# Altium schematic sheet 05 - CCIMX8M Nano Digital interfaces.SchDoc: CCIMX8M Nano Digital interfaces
size A3; PageSetup: Record=PageOptions¦CenterHorizontal=True¦CenterVertical=True¦PrintScale=0.70¦XCorrection=1.00¦YCorrection=1.00¦PrintKind=0¦BorderSize=5000000¦LeftOffset=0¦BottomOffset=0¦Orientation=2¦PaperLength=4200¦PaperWidth=2970¦Scale=100¦PaperSource=7¦PrintQuality=600¦MediaType=1¦DitherType=10¦PaperKind=A4¦PrintScaleMode=1; Author: Juan Anzola; SheetNumber: 5; SheetTotal: 21
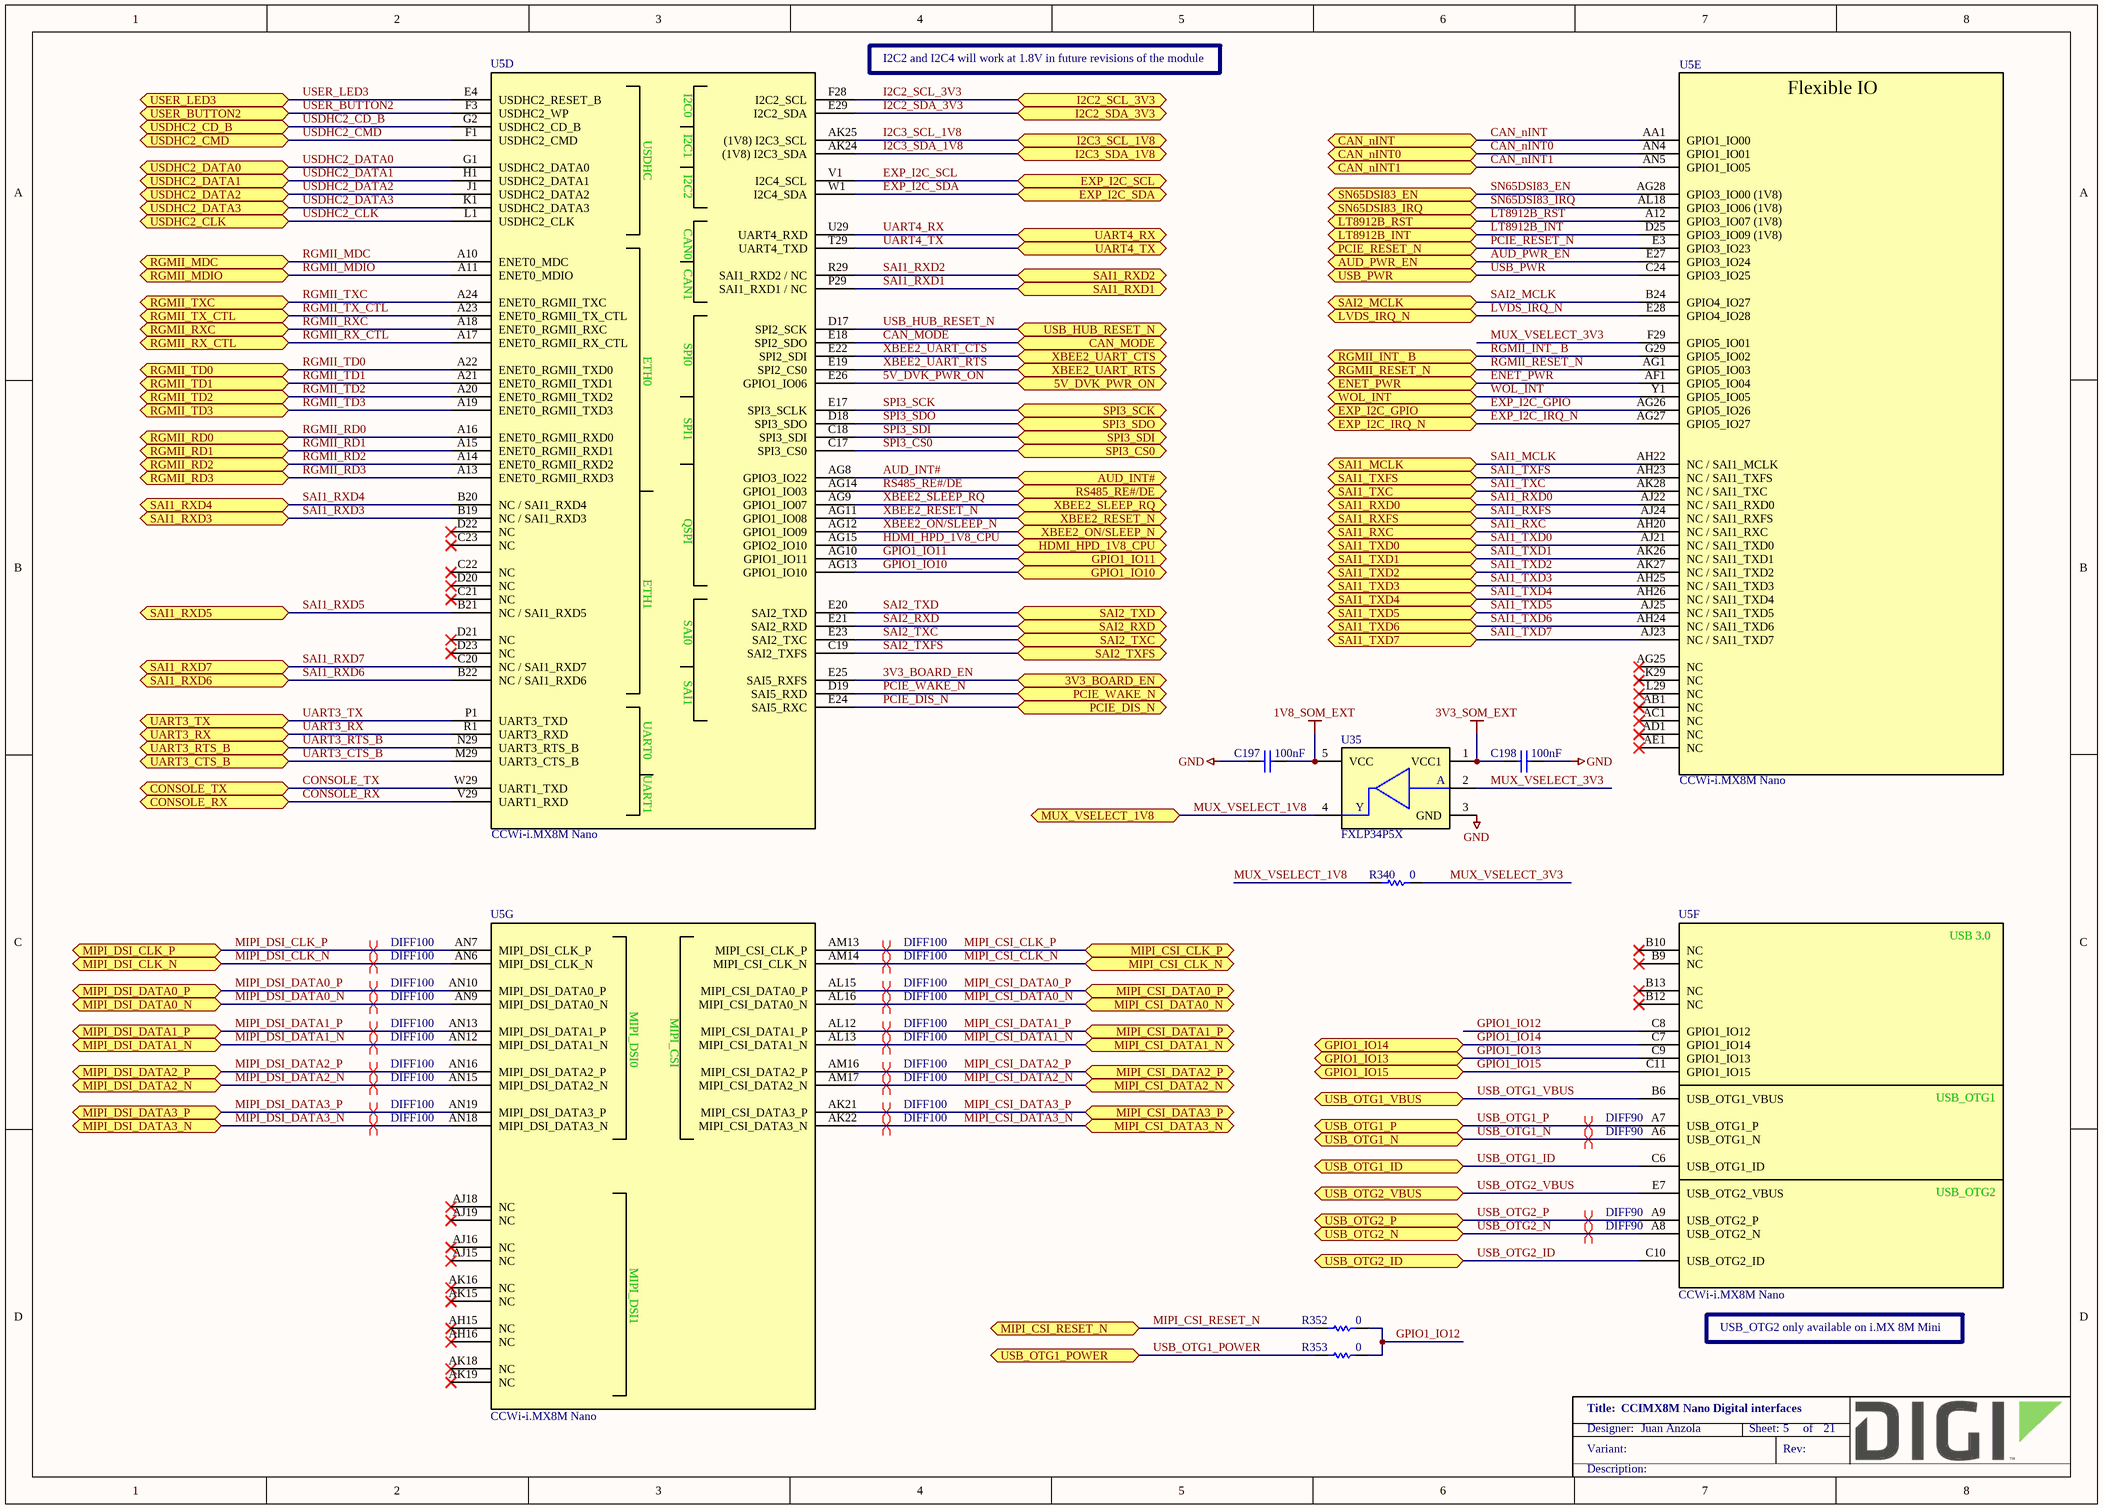
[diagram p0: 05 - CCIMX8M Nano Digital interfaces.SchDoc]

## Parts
C197  100nF  [CAPC1005X55N]
C198  100nF  [CAPC1005X55N]
R340  0  [RESC1005X40N]
R352  0  [RESC1005X40N]
R353  0  [RESC1005X40N]
U5  CCWi-i.MX8M Nano  [E-TEC_LPJ474-129M-32ABEW55L]  (parts D,E,F,G of 10)
U35  FXLP34P5X  [SOT65P210X110-5N]

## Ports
3V3_BOARD_EN (bidir), 5V_DVK_PWR_ON (bidir), AUD_INT# (bidir), AUD_PWR_EN (bidir), CAN_MODE (bidir), CAN_nINT0 (bidir), CAN_nINT1 (bidir), CAN_nINT (bidir), CONSOLE_RX (bidir), CONSOLE_TX (bidir), ENET_PWR (bidir), EXP_I2C_GPIO (bidir), EXP_I2C_IRQ_N (bidir), EXP_I2C_SCL (bidir), EXP_I2C_SDA (bidir), GPIO1_IO10 (bidir), GPIO1_IO11 (bidir), GPIO1_IO13 (bidir), GPIO1_IO14 (bidir), GPIO1_IO15 (bidir), HDMI_HPD_1V8_CPU (bidir), I2C2_SCL_3V3 (bidir), I2C2_SDA_3V3 (bidir), I2C3_SCL_1V8 (bidir), I2C3_SDA_1V8 (bidir), LT8912B_INT (bidir), LT8912B_RST (bidir), LVDS_IRQ_N (bidir), MIPI_CSI_CLK_N (bidir), MIPI_CSI_CLK_P (bidir), MIPI_CSI_DATA0_N (bidir), MIPI_CSI_DATA0_P (bidir), MIPI_CSI_DATA1_N (bidir), MIPI_CSI_DATA1_P (bidir), MIPI_CSI_DATA2_N (bidir), MIPI_CSI_DATA2_P (bidir), MIPI_CSI_DATA3_N (bidir), MIPI_CSI_DATA3_P (bidir), MIPI_CSI_RESET_N (bidir), MIPI_DSI_CLK_N (bidir), MIPI_DSI_CLK_P (bidir), MIPI_DSI_DATA0_N (bidir), MIPI_DSI_DATA0_P (bidir), MIPI_DSI_DATA1_N (bidir), MIPI_DSI_DATA1_P (bidir), MIPI_DSI_DATA2_N (bidir), MIPI_DSI_DATA2_P (bidir), MIPI_DSI_DATA3_N (bidir), MIPI_DSI_DATA3_P (bidir), MUX_VSELECT_1V8 (bidir), PCIE_DIS_N (bidir), PCIE_RESET_N (bidir), PCIE_WAKE_N (bidir), RGMII_INT_ B (bidir), RGMII_MDC (bidir), RGMII_MDIO (bidir), RGMII_RD0 (bidir), RGMII_RD1 (bidir), RGMII_RD2 (bidir), RGMII_RD3 (bidir), RGMII_RESET_N (bidir), RGMII_RX_CTL (bidir), RGMII_RXC (bidir), RGMII_TD0 (bidir), RGMII_TD1 (bidir), RGMII_TD2 (bidir), RGMII_TD3 (bidir), RGMII_TX_CTL (bidir), RGMII_TXC (bidir), RS485_RE#/DE (bidir), SAI1_MCLK (bidir), SAI1_RXC (bidir), SAI1_RXD0 (bidir), SAI1_RXD1 (bidir), SAI1_RXD2 (bidir), SAI1_RXD3 (bidir), SAI1_RXD4 (bidir), SAI1_RXD5 (bidir), SAI1_RXD6 (bidir), SAI1_RXD7 (bidir), SAI1_RXFS (bidir), SAI1_TXC (bidir), SAI1_TXD0 (bidir), SAI1_TXD1 (bidir), SAI1_TXD2 (bidir), SAI1_TXD3 (bidir), SAI1_TXD4 (bidir), SAI1_TXD5 (bidir), SAI1_TXD6 (bidir), SAI1_TXD7 (bidir), SAI1_TXFS (bidir), SAI2_MCLK (bidir), SAI2_RXD (bidir), SAI2_TXC (bidir), SAI2_TXD (bidir), SAI2_TXFS (bidir), SN65DSI83_EN (bidir), SN65DSI83_IRQ (bidir), SPI3_CS0 (bidir), SPI3_SCK (bidir), SPI3_SDI (bidir), SPI3_SDO (bidir), UART3_CTS_B (bidir), UART3_RTS_B (bidir), UART3_RX (bidir), UART3_TX (bidir), UART4_RX (bidir), UART4_TX (bidir), USB_HUB_RESET_N (bidir), USB_OTG1_ID (bidir), USB_OTG1_N (bidir), USB_OTG1_P (bidir), USB_OTG1_POWER (bidir), USB_OTG1_VBUS (bidir), USB_OTG2_ID (bidir), USB_OTG2_N (bidir), USB_OTG2_P (bidir), USB_OTG2_VBUS (bidir), USB_PWR (bidir), USDHC2_CD_B (bidir), USDHC2_CLK (bidir), USDHC2_CMD (bidir), USDHC2_DATA0 (bidir), USDHC2_DATA1 (bidir), USDHC2_DATA2 (bidir), USDHC2_DATA3 (bidir), USER_BUTTON2 (bidir), USER_LED3 (bidir), WOL_INT (bidir), XBEE2_ON/SLEEP_N (bidir), XBEE2_RESET_N (bidir), XBEE2_SLEEP_RQ (bidir), XBEE2_UART_CTS (bidir), XBEE2_UART_RTS (bidir)

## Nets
1V8_SOM_EXT: C197.2 U35.5(VCC)
3V3_SOM_EXT: C198.1 U35.1(VCC1)
GND: C197.1 C198.2 U35.3(GND)
3V3_BOARD_EN: U5.E25(SAI5_RXFS) ; port 3V3_BOARD_EN
5V_DVK_PWR_ON: U5.E26(GPIO1_IO06) ; port 5V_DVK_PWR_ON
AUD_INT#: U5.AG8(GPIO3_IO22) ; port AUD_INT#
AUD_PWR_EN: U5.E27(GPIO3_IO24) ; port AUD_PWR_EN
CAN_MODE: U5.E18(SPI2_SDO) ; port CAN_MODE
CAN_nINT: U5.AA1(GPIO1_IO00) ; port CAN_nINT
CAN_nINT0: U5.AN4(GPIO1_IO01) ; port CAN_nINT0
CAN_nINT1: U5.AN5(GPIO1_IO05) ; port CAN_nINT1
CONSOLE_RX: U5.V29(UART1_RXD) ; port CONSOLE_RX
CONSOLE_TX: U5.W29(UART1_TXD) ; port CONSOLE_TX
ENET_PWR: U5.AF1(GPIO5_IO04) ; port ENET_PWR
EXP_I2C_GPIO: U5.AG26(GPIO5_IO26) ; port EXP_I2C_GPIO
EXP_I2C_IRQ_N: U5.AG27(GPIO5_IO27) ; port EXP_I2C_IRQ_N
EXP_I2C_SCL: U5.V1(I2C4_SCL) ; port EXP_I2C_SCL
EXP_I2C_SDA: U5.W1(I2C4_SDA) ; port EXP_I2C_SDA
GPIO1_IO10: U5.AG13(GPIO1_IO10) ; port GPIO1_IO10
GPIO1_IO11: U5.AG10(GPIO1_IO11) ; port GPIO1_IO11
GPIO1_IO12: R352.2 R353.2 U5.C8(GPIO1_IO12)
GPIO1_IO13: U5.C9(GPIO1_IO13) ; port GPIO1_IO13
GPIO1_IO14: U5.C7(GPIO1_IO14) ; port GPIO1_IO14
GPIO1_IO15: U5.C11(GPIO1_IO15) ; port GPIO1_IO15
HDMI_HPD_1V8_CPU: U5.AG15(GPIO2_IO10) ; port HDMI_HPD_1V8_CPU
I2C2_SCL_3V3: U5.F28(I2C2_SCL) ; port I2C2_SCL_3V3
I2C2_SDA_3V3: U5.E29(I2C2_SDA) ; port I2C2_SDA_3V3
I2C3_SCL_1V8: U5.AK25((1V8)_I2C3_SCL) ; port I2C3_SCL_1V8
I2C3_SDA_1V8: U5.AK24((1V8)_I2C3_SDA) ; port I2C3_SDA_1V8
LT8912B_INT: U5.D25(GPIO3_IO09_(1V8)) ; port LT8912B_INT
LT8912B_RST: U5.A12(GPIO3_IO07_(1V8)) ; port LT8912B_RST
LVDS_IRQ_N: U5.E28(GPIO4_IO28) ; port LVDS_IRQ_N
MIPI_CSI_CLK_N: U5.AM14(MIPI_CSI_CLK_N) ; port MIPI_CSI_CLK_N
MIPI_CSI_CLK_P: U5.AM13(MIPI_CSI_CLK_P) ; port MIPI_CSI_CLK_P
MIPI_CSI_DATA0_N: U5.AL16(MIPI_CSI_DATA0_N) ; port MIPI_CSI_DATA0_N
MIPI_CSI_DATA0_P: U5.AL15(MIPI_CSI_DATA0_P) ; port MIPI_CSI_DATA0_P
MIPI_CSI_DATA1_N: U5.AL13(MIPI_CSI_DATA1_N) ; port MIPI_CSI_DATA1_N
MIPI_CSI_DATA1_P: U5.AL12(MIPI_CSI_DATA1_P) ; port MIPI_CSI_DATA1_P
MIPI_CSI_DATA2_N: U5.AM17(MIPI_CSI_DATA2_N) ; port MIPI_CSI_DATA2_N
MIPI_CSI_DATA2_P: U5.AM16(MIPI_CSI_DATA2_P) ; port MIPI_CSI_DATA2_P
MIPI_CSI_DATA3_N: U5.AK22(MIPI_CSI_DATA3_N) ; port MIPI_CSI_DATA3_N
MIPI_CSI_DATA3_P: U5.AK21(MIPI_CSI_DATA3_P) ; port MIPI_CSI_DATA3_P
MIPI_CSI_RESET_N: R352.1 ; port MIPI_CSI_RESET_N
MIPI_DSI_CLK_N: U5.AN6(MIPI_DSI_CLK_N) ; port MIPI_DSI_CLK_N
MIPI_DSI_CLK_P: U5.AN7(MIPI_DSI_CLK_P) ; port MIPI_DSI_CLK_P
MIPI_DSI_DATA0_N: U5.AN9(MIPI_DSI_DATA0_N) ; port MIPI_DSI_DATA0_N
MIPI_DSI_DATA0_P: U5.AN10(MIPI_DSI_DATA0_P) ; port MIPI_DSI_DATA0_P
MIPI_DSI_DATA1_N: U5.AN12(MIPI_DSI_DATA1_N) ; port MIPI_DSI_DATA1_N
MIPI_DSI_DATA1_P: U5.AN13(MIPI_DSI_DATA1_P) ; port MIPI_DSI_DATA1_P
MIPI_DSI_DATA2_N: U5.AN15(MIPI_DSI_DATA2_N) ; port MIPI_DSI_DATA2_N
MIPI_DSI_DATA2_P: U5.AN16(MIPI_DSI_DATA2_P) ; port MIPI_DSI_DATA2_P
MIPI_DSI_DATA3_N: U5.AN18(MIPI_DSI_DATA3_N) ; port MIPI_DSI_DATA3_N
MIPI_DSI_DATA3_P: U5.AN19(MIPI_DSI_DATA3_P) ; port MIPI_DSI_DATA3_P
MUX_VSELECT_1V8: R340.1 U35.4(Y) ; port MUX_VSELECT_1V8
MUX_VSELECT_3V3: R340.2 U5.F29(GPIO5_IO01) U35.2(A)
PCIE_DIS_N: U5.E24(SAI5_RXC) ; port PCIE_DIS_N
PCIE_RESET_N: U5.E3(GPIO3_IO23) ; port PCIE_RESET_N
PCIE_WAKE_N: U5.D19(SAI5_RXD) ; port PCIE_WAKE_N
RGMII_INT_ B: U5.G29(GPIO5_IO02) ; port RGMII_INT_ B
RGMII_MDC: U5.A10(ENET0_MDC) ; port RGMII_MDC
RGMII_MDIO: U5.A11(ENET0_MDIO) ; port RGMII_MDIO
RGMII_RD0: U5.A16(ENET0_RGMII_RXD0) ; port RGMII_RD0
RGMII_RD1: U5.A15(ENET0_RGMII_RXD1) ; port RGMII_RD1
RGMII_RD2: U5.A14(ENET0_RGMII_RXD2) ; port RGMII_RD2
RGMII_RD3: U5.A13(ENET0_RGMII_RXD3) ; port RGMII_RD3
RGMII_RESET_N: U5.AG1(GPIO5_IO03) ; port RGMII_RESET_N
RGMII_RX_CTL: U5.A17(ENET0_RGMII_RX_CTL) ; port RGMII_RX_CTL
RGMII_RXC: U5.A18(ENET0_RGMII_RXC) ; port RGMII_RXC
RGMII_TD0: U5.A22(ENET0_RGMII_TXD0) ; port RGMII_TD0
RGMII_TD1: U5.A21(ENET0_RGMII_TXD1) ; port RGMII_TD1
RGMII_TD2: U5.A20(ENET0_RGMII_TXD2) ; port RGMII_TD2
RGMII_TD3: U5.A19(ENET0_RGMII_TXD3) ; port RGMII_TD3
RGMII_TX_CTL: U5.A23(ENET0_RGMII_TX_CTL) ; port RGMII_TX_CTL
RGMII_TXC: U5.A24(ENET0_RGMII_TXC) ; port RGMII_TXC
RS485_RE#/DE: U5.AG14(GPIO1_IO03) ; port RS485_RE#/DE
SAI1_MCLK: U5.AH22(NC_/_SAI1_MCLK) ; port SAI1_MCLK
SAI1_RXC: U5.AH20(NC_/_SAI1_RXC) ; port SAI1_RXC
SAI1_RXD0: U5.AJ22(NC_/_SAI1_RXD0) ; port SAI1_RXD0
SAI1_RXD1: U5.P29(SAI1_RXD1_/_NC) ; port SAI1_RXD1
SAI1_RXD2: U5.R29(SAI1_RXD2_/_NC) ; port SAI1_RXD2
SAI1_RXD3: U5.B19(NC_/_SAI1_RXD3) ; port SAI1_RXD3
SAI1_RXD4: U5.B20(NC_/_SAI1_RXD4) ; port SAI1_RXD4
SAI1_RXD5: U5.B21(NC_/_SAI1_RXD5) ; port SAI1_RXD5
SAI1_RXD6: U5.B22(NC_/_SAI1_RXD6) ; port SAI1_RXD6
SAI1_RXD7: U5.C20(NC_/_SAI1_RXD7) ; port SAI1_RXD7
SAI1_RXFS: U5.AJ24(NC_/_SAI1_RXFS) ; port SAI1_RXFS
SAI1_TXC: U5.AK28(NC_/_SAI1_TXC) ; port SAI1_TXC
SAI1_TXD0: U5.AJ21(NC_/_SAI1_TXD0) ; port SAI1_TXD0
SAI1_TXD1: U5.AK26(NC_/_SAI1_TXD1) ; port SAI1_TXD1
SAI1_TXD2: U5.AK27(NC_/_SAI1_TXD2) ; port SAI1_TXD2
SAI1_TXD3: U5.AH25(NC_/_SAI1_TXD3) ; port SAI1_TXD3
SAI1_TXD4: U5.AH26(NC_/_SAI1_TXD4) ; port SAI1_TXD4
SAI1_TXD5: U5.AJ25(NC_/_SAI1_TXD5) ; port SAI1_TXD5
SAI1_TXD6: U5.AH24(NC_/_SAI1_TXD6) ; port SAI1_TXD6
SAI1_TXD7: U5.AJ23(NC_/_SAI1_TXD7) ; port SAI1_TXD7
SAI1_TXFS: U5.AH23(NC_/_SAI1_TXFS) ; port SAI1_TXFS
SAI2_MCLK: U5.B24(GPIO4_IO27) ; port SAI2_MCLK
SAI2_RXD: U5.E21(SAI2_RXD) ; port SAI2_RXD
SAI2_TXC: U5.E23(SAI2_TXC) ; port SAI2_TXC
SAI2_TXD: U5.E20(SAI2_TXD) ; port SAI2_TXD
SAI2_TXFS: U5.C19(SAI2_TXFS) ; port SAI2_TXFS
SN65DSI83_EN: U5.AG28(GPIO3_IO00_(1V8)) ; port SN65DSI83_EN
SN65DSI83_IRQ: U5.AL18(GPIO3_IO06_(1V8)) ; port SN65DSI83_IRQ
SPI3_CS0: U5.C17(SPI3_CS0) ; port SPI3_CS0
SPI3_SCK: U5.E17(SPI3_SCLK) ; port SPI3_SCK
SPI3_SDI: U5.C18(SPI3_SDI) ; port SPI3_SDI
SPI3_SDO: U5.D18(SPI3_SDO) ; port SPI3_SDO
UART3_CTS_B: U5.M29(UART3_CTS_B) ; port UART3_CTS_B
UART3_RTS_B: U5.N29(UART3_RTS_B) ; port UART3_RTS_B
UART3_RX: U5.R1(UART3_RXD) ; port UART3_RX
UART3_TX: U5.P1(UART3_TXD) ; port UART3_TX
UART4_RX: U5.U29(UART4_RXD) ; port UART4_RX
UART4_TX: U5.T29(UART4_TXD) ; port UART4_TX
USB_HUB_RESET_N: U5.D17(SPI2_SCK) ; port USB_HUB_RESET_N
USB_OTG1_ID: U5.C6(USB_OTG1_ID) ; port USB_OTG1_ID
USB_OTG1_N: U5.A6(USB_OTG1_N) ; port USB_OTG1_N
USB_OTG1_P: U5.A7(USB_OTG1_P) ; port USB_OTG1_P
USB_OTG1_POWER: R353.1 ; port USB_OTG1_POWER
USB_OTG1_VBUS: U5.B6(USB_OTG1_VBUS) ; port USB_OTG1_VBUS
USB_OTG2_ID: U5.C10(USB_OTG2_ID) ; port USB_OTG2_ID
USB_OTG2_N: U5.A8(USB_OTG2_N) ; port USB_OTG2_N
USB_OTG2_P: U5.A9(USB_OTG2_P) ; port USB_OTG2_P
USB_OTG2_VBUS: U5.E7(USB_OTG2_VBUS) ; port USB_OTG2_VBUS
USB_PWR: U5.C24(GPIO3_IO25) ; port USB_PWR
USDHC2_CD_B: U5.G2(USDHC2_CD_B) ; port USDHC2_CD_B
USDHC2_CLK: U5.L1(USDHC2_CLK) ; port USDHC2_CLK
USDHC2_CMD: U5.F1(USDHC2_CMD) ; port USDHC2_CMD
USDHC2_DATA0: U5.G1(USDHC2_DATA0) ; port USDHC2_DATA0
USDHC2_DATA1: U5.H1(USDHC2_DATA1) ; port USDHC2_DATA1
USDHC2_DATA2: U5.J1(USDHC2_DATA2) ; port USDHC2_DATA2
USDHC2_DATA3: U5.K1(USDHC2_DATA3) ; port USDHC2_DATA3
USER_BUTTON2: U5.F3(USDHC2_WP) ; port USER_BUTTON2
USER_LED3: U5.E4(USDHC2_RESET_B) ; port USER_LED3
WOL_INT: U5.Y1(GPIO5_IO05) ; port WOL_INT
XBEE2_ON/SLEEP_N: U5.AG12(GPIO1_IO09) ; port XBEE2_ON/SLEEP_N
XBEE2_RESET_N: U5.AG11(GPIO1_IO08) ; port XBEE2_RESET_N
XBEE2_SLEEP_RQ: U5.AG9(GPIO1_IO07) ; port XBEE2_SLEEP_RQ
XBEE2_UART_CTS: U5.E22(SPI2_SDI) ; port XBEE2_UART_CTS
XBEE2_UART_RTS: U5.E19(SPI2_CS0) ; port XBEE2_UART_RTS

Not connected (* = marked no-connect by the designer): U5 AB1(NC)* AC1(NC)* AD1(NC)* AE1(NC)* AG25(NC)* AH15(NC)* AH16(NC)* AJ15(NC)* AJ16(NC)* AJ18(NC)* AJ19(NC)* AK15(NC)* AK16(NC)* AK18(NC)* AK19(NC)* B9(NC)* B10(NC)* B12(NC)* B13(NC)* C21(NC)* C22(NC)* C23(NC)* D20(NC)* D21(NC)* D22(NC)* D23(NC)* K29(NC)* L29(NC)*

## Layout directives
differential pair; net class DIFF100: MIPI_CSI_CLK_N, MIPI_CSI_CLK_P, MIPI_CSI_DATA0_N, MIPI_CSI_DATA0_P, MIPI_CSI_DATA1_N, MIPI_CSI_DATA1_P, MIPI_CSI_DATA2_N, MIPI_CSI_DATA2_P, MIPI_CSI_DATA3_N, MIPI_CSI_DATA3_P, MIPI_DSI_CLK_N, MIPI_DSI_CLK_P, MIPI_DSI_DATA0_N, MIPI_DSI_DATA0_P, MIPI_DSI_DATA1_N, MIPI_DSI_DATA1_P, MIPI_DSI_DATA2_N, MIPI_DSI_DATA2_P, MIPI_DSI_DATA3_N, MIPI_DSI_DATA3_P
differential pair; net class DIFF90: USB_OTG1_N, USB_OTG1_P, USB_OTG2_N, USB_OTG2_P

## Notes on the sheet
- I2C2 and I2C4 will work at 1.8V in future revisions of the module
- USB_OTG2 only available on i.MX 8M Mini

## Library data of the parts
C197 C198 = 1000006: CAP 100nF 16V 10% X7R 0402; Part_Type: Capacitor; Manufacturer: Murata; Manufacturer_Part_Number: GRM155R71C104KA88D; Digi_PN: 14050552; Component_Life_Cycle_State: CAD Reviewed; Area: 0,95; Tolerance: 10
R340 R352 R353 = 1000076: RES 0.0 OHM 1/10W 0402 SMD; Part_Type: Resistor; Manufacturer: Panasonic - ECG; Manufacturer_Part_Number: ERJ-2GE0R00X; Digi_PN: 13050387; Component_Life_Cycle_State: Proven; Area: 0,95; Power_WV_SRF: 10
U5 = 1002739: ConnectCore for i.MX8M Nano module - LGA; Manufacturer: DIGI; Digi_PN: 50002014-01; Component_Life_Cycle_State: Pending
U35 = 1000759: TRANSLATOR 1BIT UNIDIRECT SC70-; Part_Type: IC; Manufacturer: Fairchild Semiconductor; Digi_PN: 16051662; Component_Life_Cycle_State: Reviewed; Area: 6,93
